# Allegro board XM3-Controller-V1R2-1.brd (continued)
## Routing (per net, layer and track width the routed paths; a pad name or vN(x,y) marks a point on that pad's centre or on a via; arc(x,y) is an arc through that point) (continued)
-15V: length 82
  TOP w0.178: CT81.1 242.56,22.11 ; CT81.1 240.3,23.56 ; CT81.1 242.56,22.84 ; CT81.1 241.43,23.64 ; CT81.1 242.56,23.56 ; CT81.1 240.3,22.84 ; CT81.1 240.3,22.11 ; CT81.1 241.43,22.03
  TOP w0.381: 255.78,5.18 J6.3 ; J6.3 254.66,6.3 ; J6.3 256.62,7.14 ; J6.3 256.9,6.3 ; J6.3 254.94,7.14 ; J6.3 255.78,7.42 ; J6.3 256.62,5.46 ; J6.3 254.94,5.46 ; 229.26,6.3 J4.3 ; J4.3 229.54,7.14 ; J4.3 229.54,5.46 ; J4.3 231.22,5.46 ; J4.3 231.22,7.14 ; J4.3 230.38,5.18 ; J4.3 230.38,7.42 ; J4.3 231.5,6.3 ; 242.24,5.46 J5.3 ; J5.3 241.96,6.3 ; J5.3 244.2,6.3 ; J5.3 243.92,5.46 ; J5.3 243.92,7.14 ; J5.3 243.08,5.18 ; J5.3 243.08,7.42 ; J5.3 242.24,7.14
  TOP w0.508: 238.38,13.03 238.21,13.2 DT11.2 ; RT121.2 v1(230.5,33.82)
  TOP w0.635: J10.7 4.39,31.19 3.55,30.36 3.55,27.76 5.33,25.99 12.85,25.99 CT76.1
  LAYER3 w0.508: v1(241.49,21.2) 241.49,25.92 236.73,30.69 233.63,30.69 v1(230.5,33.82)
  BOTTOM w0.178: J10.7 4.82,31.93 ; J10.7 5.4,31.77 ; J10.7 5.4,30.62 ; J10.7 4.09,31.19 ; J10.7 4.25,30.62 ; J10.7 5.56,31.19 ; J10.7 4.25,31.77 ; J10.7 4.82,30.46
  vias: v1(241.49,20.44) v1(241.49,19.68) v1(241.49,18.91) v1(241.49,18.15) v1(242.25,21.2) v1(242.25,20.44) v1(242.25,19.68) v1(242.25,18.91) v1(242.25,18.15) v1(243.01,21.2) v1(243.01,20.44) v1(243.01,19.68) v1(243.01,18.91) v1(243.01,18.15) v1(243.78,21.2) v1(243.78,20.44) v1(243.78,19.68) v1(243.78,18.91) v1(243.78,18.15) v1(244.54,21.2) v1(244.54,20.44) v1(244.54,19.68) v1(244.54,18.91) v1(244.54,18.15)
VIN: length 48.7
  TOP w0.178: QT2.5 25.3,6.34 ; QT2.5 24.22,6.89 ; QT2.5 24.22,6.34 ; QT2.5 25.3,7.45 ; QT2.5 25.3,6.89 ; QT2.5 24.76,7.45 ; QT2.5 24.76,6.34 ; QT2.5 24.22,7.45 ; 25.46,9.05 RT144.1 ; RT144.1 26.14,8.32 ; RT144.1 26.81,9.05 ; RT144.1 26.79,8.32 ; 24.22,5.07 QT2.6 ; QT2.6 24.22,5.62 ; QT2.6 24.22,6.18 ; QT2.6 25.3,5.07 ; QT2.6 24.76,6.18 ; QT2.6 25.3,5.62 ; QT2.6 25.3,6.18 ; QT2.6 24.76,5.07 ; QT2.8 25.3,3.08 ; QT2.8 24.22,3.08 ; QT2.8 24.22,3.64 ; QT2.8 25.3,2.53 ; QT2.8 24.76,2.53 ; QT2.8 24.76,3.64 ; QT2.8 24.22,2.53 ; QT2.8 25.3,3.64 ; QT2.7 25.3,3.8 ; QT2.7 25.3,4.91 ; QT2.7 24.76,4.91 ; QT2.7 24.22,3.8 ; QT2.7 24.22,4.91 ; QT2.7 24.76,3.8 ; QT2.7 24.22,4.35 ; QT2.7 25.3,4.35
  TOP w0.254: UT32.1 27.88,11.59 v1(27.37,12.1) ; RT136.1 v1(30.67,15.91)
  TOP w0.508: 12.69,6.93 J11.1 ; J11.1 13.71,6.58 ; J11.1 15.09,7.95 ; J11.1 13.71,9.33 ; J11.1 12.69,8.97 ; J11.1 12.34,7.95 ; J11.1 14.74,8.97 ; J11.1 14.74,6.93
  LAYER3 w0.254: v1(30.67,15.91) 30.67,15.4 v1(27.37,12.1) 28.38,11.09 v1(28.38,7.4)
0: length 1002.7
  TOP w0.178: 260.36,26.4 RT131.2 ; RT131.2 261.09,26.42 ; RT131.2 260.36,25.09 ; RT131.2 260.36,25.75 ; 237.83,28.99 CT74.1 ; CT74.1 239.22,29.72 ; CT74.1 239.21,28.99 ; CT74.1 238.52,30.45 ; CT74.1 237.81,29.72 ; CT74.1 237.83,30.45 ; CT74.1 239.21,30.45 ; 226.73,32.37 CT71.2 ; CT71.2 226.73,33.83 ; CT71.2 226.71,33.1 ; CT71.2 228.11,33.83 ; CT71.2 227.42,33.83 ; 247.55,27.55 CT79.1 ; CT79.1 247.55,28.24 ; CT79.1 247.55,26.86 ; CT79.1 248.28,26.85 ; CT75.2 248.94,29.64 ; CT75.2 247.55,29.64 ; CT75.2 247.54,28.91 ; CT75.2 247.55,28.18 ; CT75.2 248.25,29.64 ; CT75.2 248.95,28.91 ; 240.3,25.84 CT81.2 ; CT81.2 240.3,25.11 ; CT81.2 241.43,26.64 ; CT81.2 242.56,26.56 ; CT81.2 242.56,25.11 ; CT81.2 240.3,26.56 ; CT81.2 241.43,25.03 ; CT81.2 242.56,25.84 ; CT80.1 259.6,26.26 ; CT80.1 258.91,24.8 ; CT80.1 260.29,24.8 ; CT80.1 260.3,25.53 ; CT80.1 258.91,26.26 ; CT80.1 260.29,26.26 ; CT80.1 258.9,25.53 ; 237.84,28.45 RT126.1 ; RT126.1 239.17,29.18 ; RT126.1 239.2,28.45 ; RT126.1 237.86,29.18 ; 239.27,29.94 RT123.2 ; RT123.2 239.27,30.59 ; RT123.2 239.27,29.28 ; RT123.2 240,30.62 ; 226.73,32.43 CT73.1 ; CT73.1 226.73,31.05 ; CT73.1 226.73,31.74 ; CT73.1 227.46,31.04 ; RT134.1 260.28,24.26 ; RT134.1 258.92,24.26 ; RT134.1 260.26,24.99 ; RT134.1 258.94,24.99
  TOP w0.254: UT14.1 102.21,68 ; UT14.4 104.39,68.66 v1(104.65,68.91) ; UT15.1 108.81,68 ; v1(117.85,68.91) 117.6,68.66 UT16.4 ; v1(111.25,68.91) 111,68.66 UT15.4 ; CT86.2 33.77,15.77 v1(33.88,15.66) CT87.2 ; UT32.5 27.77,9.56 v1(27.56,9.35) ; CT88.2 v1(28.76,16.42) ; UT16.1 115.42,68
  TOP w0.381: UT23.8 108.23,45.02 108.2,45.04 ; 101.34,45.04 101.98,45.04 v1(102.61,44.4) ; 101.34,45.04 100.71,45.04 ; 101.34,45.04 101.35,45.04 UT22.1 ; v1(104.27,39.87) CT65.2 101.7,39.87 100.7,38.87 UT22.19 ; 100.71,45.04 100.32,45.04 100.05,44.77 UT22.3 ; 100.71,45.04 100.7,45.03 UT22.2 ; UT25.8 v1(185.6,37.62) ; UT24.8 130.75,38.23 131.19,37.8 v1(131.19,37.67) ; CT46.2 114.55,67.9 114.81,67.64 v1(115.06,67.64) 115.42,68 ; RT89.2 v1(130.3,65.77) 130.3,65.78 CT49.2 ; CT44.2 101.34,67.9 101.6,67.64 v1(101.85,67.64) 102.21,68 ; CT43.1 RT82.1 v1(125.18,73.07) ; UT22.10 v1(94.52,43.92) ; RT114.1 142.87,40.85 v1(143,40.97) ; v1(28.76,16.42) 28.68,16.33 27.94,16.33 26.14,14.53 RT140.2 ; 108.81,68 v1(108.46,67.64) 108.2,67.64 107.95,67.9 CT45.2 ; 109.47,45.04 109.53,44.99 UT23.6 ; 109.47,45.04 110.11,45.04 110.18,44.97 UT23.5 ; 109.47,45.04 108.84,45.04 ; CT60.2 v1(133.6,44.66) ; CT67.2 CT64.2 v1(174.5,39.58) ; 107.57,45.04 108.2,45.04 ; 107.57,45.04 106.55,45.04 106.14,44.63 v1(106.14,43.92) UT23.10 ; 107.57,45.04 107.58,45.03 UT23.9 ; 108.2,45.04 108.84,45.04 ; 181.32,45.47 181.32,48.94 UT13.20 ; 181.32,45.47 RT111.1 ; 181.32,45.47 180.99,45.8 v1(179.83,45.8) 179.54,45.8 CT61.2 ; 108.84,45.04 108.88,45 UT23.7 ; RT101.2 v1(122.33,59.82) ; UT19.8 v1(113.54,57.87) ; v1(115.66,39.87) CT66.2 114.39,39.83 112.77,39.83 112.13,39.18 UT23.19 ; CT50.2 v1(119,65.4) ; UT23.1 113.76,43.92 v1(114.17,43.51) ; UT20.8 v1(134.62,56.54)
  TOP w0.508: v1(121.65,83.32) CT18.1 122.07,81.93 UT6.2 ; RT37.1 94.21,82.56 CT14.2 v1(97.22,82.65) 97.22,81.88 97.24,81.86 97.24,81.39 CT19.2 97.26,81.03 96.71,80.49 UT10.2 ; UT9.2 166.74,81.05 166.19,81.59 CT22.2 165.84,81.58 165.37,81.58 165.34,81.55 v1(164.58,81.55) CT33.2 164.67,78.54 RT55.1 ; v1(101.9,83.32) CT15.1 102.32,81.93 UT3.2 ; UT11.4 v1(31.62,81.74) ; 189.19,61.75 189.48,62.04 UT18.2 ; 189.19,61.75 189.15,61.78 188.43,61.78 v1(188.34,61.87) ; 189.19,61.75 CT54.1 ; CT9.2 v1(116.21,84.47) ; v1(188.34,85.19) 188.43,85.1 189.15,85.1 189.19,85.07 ; UT5.2 115.49,81.93 CT17.1 v1(115.07,83.32) ; UT21.2 121.42,48.56 CT59.2 RT107.2 v1(121.42,52.42) ; 189.19,73.41 CT38.1 ; 189.19,73.41 189.48,73.7 UT12.2 ; 189.19,73.41 189.15,73.44 188.43,73.44 v1(188.34,73.53) ; UT8.2 158.14,81.05 157.59,81.59 CT21.2 157.24,81.58 156.77,81.58 156.74,81.55 v1(155.98,81.55) CT32.2 156.07,78.54 RT53.1 ; CT10.2 v1(122.79,84.47) ; CT7.2 v1(103.04,84.47) ; RT137.1 v1(230.29,13.2) ; UT7.2 149.54,81.05 149,81.59 CT20.2 148.64,81.58 148.17,81.58 148.14,81.55 v1(147.38,81.55) CT31.2 147.47,78.54 RT51.1 ; v1(188.34,96.85) 188.43,96.76 189.15,96.76 189.19,96.73 ; CT39.2 v1(30.14,70.82) UT17.1 ; UT2.2 189.48,85.36 189.19,85.07 ; DT3.2 DT2.2 ; DT2.2 v1(70.59,87.33) ; DT2.2 DT1.2 ; v1(108.48,83.32) CT16.1 108.9,81.93 UT4.2 ; RT4.1 v1(193.84,95.49) ; CT11.2 v1(150.36,83.53) ; CT48.2 v1(185.67,64.88) ; 189.19,96.73 CT3.1 ; 189.19,96.73 189.48,97.02 UT1.2 ; CT12.2 v1(158.95,83.53) ; CT8.2 v1(109.63,84.47) ; CT1.2 v1(185.67,99.86) ; DT12.2 v1(247.05,13.2) ; v1(227.16,35.88) RT117.2 CT69.2 231.02,35.88 UT28.2 ; 189.19,85.07 CT6.1 ; UT30.2 264.53,26.36 CT77.2 RT124.2 v1(263.4,29.03) ; CT4.2 v1(185.67,88.2) ; CT30.2 v1(99.2,79.67) ; CT35.2 v1(185.67,76.54) ; CT13.2 v1(167.55,83.53)
  TOP w0.635: CT72.2 CT76.2 18.14,27.53 v1(20.32,25.35) ; RT72.2 148.14,75.26 v1(146.56,75.26) ; v1(155.16,75.26) 156.74,75.26 RT73.2 ; v1(163.75,75.26) 165.34,75.26 RT74.2 ; v1(90.93,83.47) 90.93,81.89 RT36.2 ; UT27.2 74.76,38.81 75.38,39.44 CT62.2 CT68.2 ; UT26.2 57.92,38.81 CT63.2 CT70.2 ; 71.63,46.81 v1(69.98,46.81) ; DT4.2 v1(51.94,46.81)
  GND1 w0.178: J10.3 4.82,29.24 ; J10.3 5.41,28.65 ; J10.3 4.82,28.07 ; J10.3 4.24,28.65 ; J10.3 5.29,28.19 ; J10.3 5.29,29.12 ; J10.3 4.36,28.19 ; J10.3 4.36,29.12 ; 6.15,29.92 J10.5 ; J10.5 7.31,29.92 ; J10.5 6.73,30.51 ; J10.5 6.73,29.34 ; J10.5 7.19,29.46 ; J10.5 6.27,30.39 ; J10.5 7.19,30.39 ; J10.5 6.27,29.46 ; 6.73,39.5 J10.21 ; J10.21 7.31,40.08 ; J10.21 6.15,40.08 ; J10.21 7.19,40.55 ; J10.21 6.27,40.55 ; J10.21 6.73,40.67 ; J10.21 6.27,39.62 ; J10.21 7.19,39.62 ; UT13.84 152.6,95.71 ; UT13.84 153.44,95.43 ; UT13.84 153.44,93.75 ; UT13.84 153.72,94.59 ; UT13.84 151.76,95.43 ; UT13.84 151.76,93.75 ; UT13.84 151.48,94.59 ; UT13.84 152.6,93.47 ; J3.16 182.95,20.54 ; J3.16 182.95,22.22 ; J3.16 181.27,20.54 ; J3.16 182.11,20.26 ; J3.16 182.11,22.5 ; J3.16 183.23,21.38 ; J3.16 180.99,21.38 ; J3.16 181.27,22.22 ; 4.24,41.35 4.82,41.35 ; 4.82,41.35 5.41,41.35 ; 4.82,41.35 5.29,40.89 ; 4.82,41.35 5.29,41.82 ; 4.82,41.35 4.36,41.82 ; 4.82,41.35 4.82,40.77 ; 4.82,41.35 4.36,40.89 ; 4.82,41.35 4.82,41.94 ; 178.94,91.16 UT13.22 ; UT13.22 179.78,91.44 ; UT13.22 178.1,93.12 ; UT13.22 178.94,93.4 ; UT13.22 178.1,91.44 ; UT13.22 177.82,92.28 ; UT13.22 179.78,93.12 ; UT13.22 180.06,92.28 ; 183.81,22.22 J3.14 ; J3.14 185.49,22.22 ; J3.14 184.65,22.5 ; J3.14 184.65,20.26 ; J3.14 185.49,20.54 ; J3.14 183.53,21.38 ; J3.14 185.77,21.38 ; J3.14 183.81,20.54 ; 4.82,33.15 J10.11 ; J10.11 4.24,33.73 ; J10.11 5.41,33.73 ; J10.11 4.36,34.2 ; J10.11 5.29,34.2 ; J10.11 4.82,34.32 ; J10.11 4.36,33.27 ; J10.11 5.29,33.27 ; 74.35,22.22 J1.12 ; J1.12 76.31,21.38 ; J1.12 74.07,21.38 ; J1.12 74.35,20.54 ; J1.12 75.19,22.5 ; J1.12 75.19,20.26 ; J1.12 76.03,20.54 ; J1.12 76.03,22.22 ; 84.12,90.58 UT13.101 ; UT13.101 84.96,88.62 ; UT13.101 85.8,90.58 ; UT13.101 84.12,88.9 ; UT13.101 86.08,89.74 ; UT13.101 85.8,88.9 ; UT13.101 83.84,89.74 ; UT13.101 84.96,90.86 ; 117.14,48.26 UT13.60 ; UT13.60 117.14,49.94 ; UT13.60 117.98,47.98 ; UT13.60 118.82,49.94 ; UT13.60 116.86,49.1 ; UT13.60 117.98,50.22 ; UT13.60 119.1,49.1 ; UT13.60 118.82,48.26 ; 4.36,36.74 J10.15 ; J10.15 5.29,35.81 ; J10.15 4.36,35.81 ; J10.15 4.82,35.69 ; J10.15 5.41,36.27 ; J10.15 4.24,36.27 ; J10.15 5.29,36.74 ; J10.15 4.82,36.86 ; J1.2 87.89,22.5 ; J1.2 87.05,20.54 ; J1.2 89.01,21.38 ; J1.2 87.89,20.26 ; J1.2 88.73,22.22 ; J1.2 87.05,22.22 ; J1.2 86.77,21.38 ; J1.2 88.73,20.54 ; UT13.82 155.14,95.71 ; UT13.82 155.98,95.43 ; UT13.82 155.98,93.75 ; UT13.82 154.3,93.75 ; UT13.82 156.26,94.59 ; UT13.82 155.14,93.47 ; UT13.82 154.02,94.59 ; UT13.82 154.3,95.43 ; J1.16 70.11,22.5 ; J1.16 70.95,20.54 ; J1.16 70.11,20.26 ; J1.16 68.99,21.38 ; J1.16 70.95,22.22 ; J1.16 69.27,22.22 ; J1.16 69.27,20.54 ; J1.16 71.23,21.38 ; 130.07,21.38 J2.12 ; J2.12 132.31,21.38 ; J2.12 132.03,20.54 ; J2.12 130.35,20.54 ; J2.12 131.19,20.26 ; J2.12 132.03,22.22 ; J2.12 130.35,22.22 ; J2.12 131.19,22.5 ; 150.06,93.47 UT13.86 ; UT13.86 148.94,94.59 ; UT13.86 150.9,95.43 ; UT13.86 149.22,93.75 ; UT13.86 150.06,95.71 ; UT13.86 151.18,94.59 ; UT13.86 149.22,95.43 ; UT13.86 150.9,93.75 ; J2.16 127.23,21.38 ; J2.16 126.11,20.26 ; J2.16 125.27,20.54 ; J2.16 126.95,20.54 ; J2.16 124.99,21.38 ; J2.16 126.95,22.22 ; J2.16 125.27,22.22 ; J2.16 126.11,22.5 ; 89.2,48.26 UT13.104 ; UT13.104 90.04,50.22 ; UT13.104 91.16,49.1 ; UT13.104 90.88,49.94 ; UT13.104 89.2,49.94 ; UT13.104 90.04,47.98 ; UT13.104 88.92,49.1 ; UT13.104 90.88,48.26 ; 84.96,78.46 UT13.98 ; UT13.98 85.8,78.74 ; UT13.98 85.8,80.42 ; UT13.98 84.12,80.42 ; UT13.98 84.12,78.74 ; UT13.98 86.08,79.58 ; UT13.98 84.96,80.7 ; UT13.98 83.84,79.58 ; J10.17 6.73,38.13 ; J10.17 7.19,37.08 ; J10.17 6.73,36.96 ; J10.17 6.27,38.01 ; J10.17 6.15,37.54 ; J10.17 6.27,37.08 ; J10.17 7.31,37.54 ; J10.17 7.19,38.01 ; 72.65,20.26 J1.14 ; J1.14 72.65,22.5 ; J1.14 73.49,22.22 ; J1.14 73.49,20.54 ; J1.14 71.81,22.22 ; J1.14 71.81,20.54 ; J1.14 73.77,21.38 ; J1.14 71.53,21.38 ; 6.73,31.88 J10.9 ; J10.9 7.19,32.93 ; J10.9 7.31,32.46 ; J10.9 7.19,32 ; J10.9 6.15,32.46 ; J10.9 6.27,32.93 ; J10.9 6.27,32 ; J10.9 6.73,33.05 ; 127.81,22.22 J2.14 ; J2.14 127.81,20.54 ; J2.14 128.65,20.26 ; J2.14 128.65,22.5 ; J2.14 129.49,22.22 ; J2.14 129.77,21.38 ; J2.14 129.49,20.54 ; J2.14 127.53,21.38 ; 89.2,93.98 UT13.107 ; UT13.107 90.04,93.7 ; UT13.107 89.2,95.66 ; UT13.107 90.88,93.98 ; UT13.107 90.88,95.66 ; UT13.107 91.16,94.82 ; UT13.107 88.92,94.82 ; UT13.107 90.04,95.94 ; UT13.103 88.34,48.26 ; UT13.103 88.62,49.1 ; UT13.103 86.38,49.1 ; UT13.103 87.5,47.98 ; UT13.103 87.5,50.22 ; UT13.103 88.34,49.94 ; UT13.103 86.66,48.26 ; UT13.103 86.66,49.94 ; 146.68,95.43 UT13.88 ; UT13.88 148.64,94.59 ; UT13.88 148.36,93.75 ; UT13.88 147.52,93.47 ; UT13.88 147.52,95.71 ; UT13.88 146.68,93.75 ; UT13.88 148.36,95.43 ; UT13.88 146.4,94.59 ; UT13.20 181.48,50.22 ; UT13.20 180.64,49.94 ; UT13.20 181.48,47.98 ; UT13.20 182.32,48.26 ; UT13.20 182.32,49.94 ; UT13.20 180.36,49.1 ; UT13.20 180.64,48.26 ; UT13.20 182.6,49.1 ; J3.2 200.73,20.54 ; J3.2 199.05,22.22 ; J3.2 199.89,20.26 ; J3.2 198.77,21.38 ; J3.2 201.01,21.38 ; J3.2 199.05,20.54 ; J3.2 200.73,22.22 ; J3.2 199.89,22.5 ; 115.44,91.16 UT13.62 ; UT13.62 114.32,92.28 ; UT13.62 114.6,91.44 ; UT13.62 116.28,93.12 ; UT13.62 116.56,92.28 ; UT13.62 114.6,93.12 ; UT13.62 116.28,91.44 ; UT13.62 115.44,93.4 ; UT13.93 86.08,64.34 ; UT13.93 83.84,64.34 ; UT13.93 84.96,65.46 ; UT13.93 84.12,63.5 ; UT13.93 85.8,63.5 ; UT13.93 84.12,65.18 ; UT13.93 84.96,63.22 ; UT13.93 85.8,65.18 ; 142.77,21.38 J2.2 ; J2.2 144.73,22.22 ; J2.2 143.05,22.22 ; J2.2 145.01,21.38 ; J2.2 143.89,20.26 ; J2.2 143.05,20.54 ; J2.2 144.73,20.54 ; J2.2 143.89,22.5 ; 4.36,38.35 J10.19 ; J10.19 4.36,39.28 ; J10.19 5.29,38.35 ; J10.19 4.82,39.4 ; J10.19 5.29,39.28 ; J10.19 4.24,38.81 ; J10.19 5.41,38.81 ; J10.19 4.82,38.23 ; 186.07,21.38 J3.12 ; J3.12 187.19,20.26 ; J3.12 188.03,22.22 ; J3.12 186.35,20.54 ; J3.12 188.03,20.54 ; J3.12 186.35,22.22 ; J3.12 187.19,22.5 ; J3.12 188.31,21.38 ; UT13.106 88.34,93.98 ; UT13.106 87.5,95.94 ; UT13.106 88.34,95.66 ; UT13.106 86.38,94.82 ; UT13.106 86.66,93.98 ; UT13.106 86.66,95.66 ; UT13.106 88.62,94.82 ; UT13.106 87.5,93.7 ; 6.27,42.16 J10.25 ; J10.25 7.19,43.09 ; J10.25 7.31,42.62 ; J10.25 6.73,42.04 ; J10.25 6.27,43.09 ; J10.25 7.19,42.16 ; J10.25 6.15,42.62 ; J10.25 6.73,43.21 ; J10.13 6.73,35.59 ; J10.13 7.19,35.47 ; J10.13 7.19,34.54 ; J10.13 6.15,35 ; J10.13 7.31,35 ; J10.13 6.27,34.54 ; J10.13 6.73,34.42 ; J10.13 6.27,35.47 ; 8.63,28.65 9.1,28.19 ; 8.63,28.65 8.63,28.07 ; 8.63,28.65 8.63,29.24 ; 8.63,28.65 9.22,28.65 ; 8.63,28.65 8.17,28.19 ; 8.63,28.65 8.05,28.65 ; 8.63,28.65 9.1,29.12 ; 8.63,28.65 8.17,29.12
  GND1 w0.508: J11.2 8.74,6.93 ; J11.2 7.72,6.58 ; J11.2 8.74,8.97 ; J11.2 6.7,6.93 ; J11.2 6.35,7.95 ; J11.2 7.72,9.33 ; J11.2 6.7,8.97 ; J11.2 9.09,7.95 ; J11.3 10.72,4.63 ; J11.3 9.7,2.23 ; J11.3 12.09,3.25 ; J11.3 11.74,4.28 ; J11.3 11.74,2.23 ; J11.3 9.35,3.25 ; J11.3 10.72,1.88 ; J11.3 9.7,4.28
  GND1 w0.559: UT27.2 74.24,38.81 ; UT27.2 73.93,37.89 ; UT27.2 72.09,39.73 ; UT27.2 72.09,37.89 ; UT27.2 73.93,39.73 ; UT27.2 71.78,38.81 ; J12.2 44.66,7.24 ; J12.2 43.81,9.2 ; J12.2 42.97,7.24 ; J12.2 44.93,8.08 ; J12.2 42.7,8.08 ; J12.2 43.81,6.96 ; J12.2 44.66,8.92 ; J12.2 42.97,8.92 ; 42.97,17.3 J13.2 ; J13.2 44.93,16.46 ; J13.2 43.81,17.58 ; J13.2 42.97,15.62 ; J13.2 42.7,16.46 ; J13.2 44.66,17.3 ; J13.2 43.81,15.34 ; J13.2 44.66,15.62 ; UT26.2 56.15,37.89 ; UT26.2 54.31,39.73 ; UT26.2 56.15,39.73 ; UT26.2 54,38.81 ; UT26.2 56.46,38.81 ; UT26.2 54.31,37.89
  GND2 w0.178: 117.98,48.03 UT13.60 ; UT13.60 119.05,49.1 ; UT13.60 117.98,50.17 ; UT13.60 117.18,48.3 ; UT13.60 118.79,48.3 ; UT13.60 117.18,49.91 ; UT13.60 116.91,49.1 ; UT13.60 118.79,49.91 ; 84.96,63.27 UT13.93 ; UT13.93 84.16,63.54 ; UT13.93 85.77,65.15 ; UT13.93 84.96,65.41 ; UT13.93 83.89,64.34 ; UT13.93 85.77,63.54 ; UT13.93 86.03,64.34 ; UT13.93 84.16,65.15 ; 127.84,20.58 J2.14 ; J2.14 129.72,21.38 ; J2.14 127.58,21.38 ; J2.14 128.65,22.45 ; J2.14 128.65,20.31 ; J2.14 129.46,22.19 ; J2.14 127.84,22.19 ; J2.14 129.46,20.58 ; UT13.101 85.77,88.94 ; UT13.101 86.03,89.74 ; UT13.101 84.96,90.81 ; UT13.101 85.77,90.55 ; UT13.101 84.16,90.55 ; UT13.101 84.96,88.67 ; UT13.101 84.16,88.94 ; UT13.101 83.89,89.74 ; UT13.86 150.86,95.39 ; UT13.86 149.25,95.39 ; UT13.86 150.06,93.52 ; UT13.86 149.25,93.78 ; UT13.86 150.06,95.65 ; UT13.86 150.86,93.78 ; UT13.86 148.99,94.59 ; UT13.86 151.13,94.59 ; 126.11,20.31 J2.16 ; J2.16 125.04,21.38 ; J2.16 126.92,22.19 ; J2.16 125.3,20.58 ; J2.16 127.18,21.38 ; J2.16 125.3,22.19 ; J2.16 126.92,20.58 ; J2.16 126.11,22.45 ; 6.3,32.89 J10.9 ; J10.9 7.16,32.04 ; J10.9 7.16,32.89 ; J10.9 6.3,32.04 ; J1.12 76,20.58 ; J1.12 75.19,22.45 ; J1.12 76,22.19 ; J1.12 75.19,20.31 ; J1.12 76.26,21.38 ; J1.12 74.12,21.38 ; J1.12 74.38,22.19 ; J1.12 74.38,20.58 ; J10.5 7.16,30.35 ; J10.5 6.3,29.5 ; J10.5 7.16,29.5 ; J10.5 6.3,30.35 ; 6.3,42.2 J10.25 ; J10.25 7.16,42.2 ; J10.25 7.16,43.05 ; J10.25 6.3,43.05 ; UT13.22 179.75,93.09 ; UT13.22 178.14,91.48 ; UT13.22 179.75,91.48 ; UT13.22 177.87,92.28 ; UT13.22 178.94,91.21 ; UT13.22 180.01,92.28 ; UT13.22 178.94,93.35 ; UT13.22 178.14,93.09 ; 198.82,21.38 J3.2 ; J3.2 199.89,22.45 ; J3.2 200.7,20.58 ; J3.2 200.96,21.38 ; J3.2 199.89,20.31 ; J3.2 199.08,20.58 ; J3.2 199.08,22.19 ; J3.2 200.7,22.19 ; 143.08,20.58 J2.2 ; J2.2 143.89,20.31 ; J2.2 144.7,22.19 ; J2.2 144.7,20.58 ; J2.2 142.82,21.38 ; J2.2 143.08,22.19 ; J2.2 144.96,21.38 ; J2.2 143.89,22.45 ; J3.14 184.65,22.45 ; J3.14 183.84,22.19 ; J3.14 183.58,21.38 ; J3.14 185.46,22.19 ; J3.14 185.72,21.38 ; J3.14 185.46,20.58 ; J3.14 184.65,20.31 ; J3.14 183.84,20.58 ; 83.89,79.58 UT13.98 ; UT13.98 84.96,80.65 ; UT13.98 84.96,78.51 ; UT13.98 86.03,79.58 ; UT13.98 84.16,80.39 ; UT13.98 85.77,80.39 ; UT13.98 84.16,78.78 ; UT13.98 85.77,78.78 ; 152.6,93.52 UT13.84 ; UT13.84 153.67,94.59 ; UT13.84 152.6,95.65 ; UT13.84 153.4,95.39 ; UT13.84 153.4,93.78 ; UT13.84 151.53,94.59 ; UT13.84 151.79,93.78 ; UT13.84 151.79,95.39 ; UT13.20 182.29,48.3 ; UT13.20 181.48,50.17 ; UT13.20 180.41,49.1 ; UT13.20 180.68,49.91 ; UT13.20 182.29,49.91 ; UT13.20 180.68,48.3 ; UT13.20 182.55,49.1 ; UT13.20 181.48,48.03 ; 69.3,22.19 J1.16 ; J1.16 69.3,20.58 ; J1.16 70.11,20.31 ; J1.16 71.18,21.38 ; J1.16 70.11,22.45 ; J1.16 70.92,22.19 ; J1.16 70.92,20.58 ; J1.16 69.04,21.38 ; 4.4,33.31 J10.11 ; J10.11 5.25,34.16 ; J10.11 5.25,33.31 ; J10.11 4.4,34.16 ; 89.24,48.3 UT13.104 ; UT13.104 89.24,49.91 ; UT13.104 90.85,48.3 ; UT13.104 90.85,49.91 ; UT13.104 88.97,49.1 ; UT13.104 91.11,49.1 ; UT13.104 90.04,48.03 ; UT13.104 90.04,50.17 ; 6.3,39.66 J10.21 ; J10.21 7.16,39.66 ; J10.21 6.3,40.51 ; J10.21 7.16,40.51 ; 8.63,28.65 9.06,29.08 ; 8.63,28.65 8.21,29.08 ; 8.63,28.65 9.06,28.23 ; 8.63,28.65 8.21,28.23 ; UT13.62 116.25,91.48 ; UT13.62 116.51,92.28 ; UT13.62 114.64,91.48 ; UT13.62 114.64,93.09 ; UT13.62 115.44,91.21 ; UT13.62 115.44,93.35 ; UT13.62 116.25,93.09 ; UT13.62 114.37,92.28 ; J10.13 7.16,35.43 ; J10.13 6.3,34.58 ; J10.13 7.16,34.58 ; J10.13 6.3,35.43 ; 147.52,93.52 UT13.88 ; UT13.88 147.52,95.65 ; UT13.88 146.71,95.39 ; UT13.88 148.59,94.59 ; UT13.88 146.45,94.59 ; UT13.88 146.71,93.78 ; UT13.88 148.32,95.39 ; UT13.88 148.32,93.78 ; J10.15 5.25,35.85 ; J10.15 5.25,36.7 ; J10.15 4.4,35.85 ; J10.15 4.4,36.7 ; UT13.82 155.94,95.39 ; UT13.82 155.14,93.52 ; UT13.82 155.14,95.65 ; UT13.82 154.33,93.78 ; UT13.82 154.07,94.59 ; UT13.82 155.94,93.78 ; UT13.82 156.21,94.59 ; UT13.82 154.33,95.39 ; J1.14 72.65,22.45 ; J1.14 73.46,20.58 ; J1.14 71.84,22.19 ; J1.14 71.58,21.38 ; J1.14 73.46,22.19 ; J1.14 72.65,20.31 ; J1.14 71.84,20.58 ; J1.14 73.72,21.38 ; 89.24,94.02 UT13.107 ; UT13.107 90.85,95.63 ; UT13.107 89.24,95.63 ; UT13.107 91.11,94.82 ; UT13.107 90.85,94.02 ; UT13.107 88.97,94.82 ; UT13.107 90.04,95.89 ; UT13.107 90.04,93.75 ; 86.7,48.3 UT13.103 ; UT13.103 86.43,49.1 ; UT13.103 88.57,49.1 ; UT13.103 87.5,48.03 ; UT13.103 88.31,49.91 ; UT13.103 87.5,50.17 ; UT13.103 86.7,49.91 ; UT13.103 88.31,48.3 ; 4.4,29.08 J10.3 ; J10.3 4.4,28.23 ; J10.3 5.25,28.23 ; J10.3 5.25,29.08 ; 186.38,22.19 J3.12 ; J3.12 188,22.19 ; J3.12 187.19,22.45 ; J3.12 188,20.58 ; J3.12 186.38,20.58 ; J3.12 186.12,21.38 ; J3.12 188.26,21.38 ; J3.12 187.19,20.31 ; 181.3,22.19 J3.16 ; J3.16 181.3,20.58 ; J3.16 183.18,21.38 ; J3.16 182.92,22.19 ; J3.16 182.92,20.58 ; J3.16 181.04,21.38 ; J3.16 182.11,20.31 ; J3.16 182.11,22.45 ; J1.2 88.7,22.19 ; J1.2 88.96,21.38 ; J1.2 87.89,22.45 ; J1.2 87.08,22.19 ; J1.2 88.7,20.58 ; J1.2 86.82,21.38 ; J1.2 87.89,20.31 ; J1.2 87.08,20.58 ; J2.12 131.19,22.45 ; J2.12 132.26,21.38 ; J2.12 130.12,21.38 ; J2.12 131.19,20.31 ; J2.12 130.38,20.58 ; J2.12 132,20.58 ; J2.12 130.38,22.19 ; J2.12 132,22.19 ; 4.4,38.39 J10.19 ; J10.19 5.25,39.24 ; J10.19 5.25,38.39 ; J10.19 4.4,39.24 ; 4.82,41.35 5.25,41.78 ; 4.82,41.35 5.25,40.93 ; 4.82,41.35 4.4,40.93 ; 4.82,41.35 4.4,41.78 ; 87.5,93.75 UT13.106 ; UT13.106 86.43,94.82 ; UT13.106 87.5,95.89 ; UT13.106 88.31,95.63 ; UT13.106 86.7,95.63 ; UT13.106 88.31,94.02 ; UT13.106 88.57,94.82 ; UT13.106 86.7,94.02 ; J10.17 7.16,37.97 ; J10.17 7.16,37.12 ; J10.17 6.3,37.97 ; J10.17 6.3,37.12
  GND2 w0.508: J11.2 8.71,8.94 ; J11.2 6.4,7.95 ; J11.2 7.72,9.27 ; J11.2 6.74,8.94 ; J11.2 7.72,6.63 ; J11.2 8.71,6.97 ; J11.2 9.04,7.95 ; J11.2 6.74,6.97 ; J11.3 11.7,4.24 ; J11.3 11.7,2.27 ; J11.3 10.72,1.93 ; J11.3 9.73,2.27 ; J11.3 9.4,3.25 ; J11.3 9.73,4.24 ; J11.3 12.04,3.25 ; J11.3 10.72,4.58
  GND2 w0.559: UT26.2 56.12,37.93 ; UT26.2 54.35,39.7 ; UT26.2 56.41,38.81 ; UT26.2 56.12,39.7 ; UT26.2 54.35,37.93 ; UT26.2 54.05,38.81 ; J13.2 43.81,17.53 ; J13.2 44.62,17.27 ; J13.2 44.88,16.46 ; J13.2 44.62,15.66 ; J13.2 43.81,15.39 ; J13.2 42.75,16.46 ; J13.2 43.01,15.66 ; J13.2 43.01,17.27 ; UT27.2 74.19,38.81 ; UT27.2 73.9,37.93 ; UT27.2 71.83,38.81 ; UT27.2 72.13,37.93 ; UT27.2 72.13,39.7 ; UT27.2 73.9,39.7 ; J12.2 43.81,9.15 ; J12.2 43.01,8.89 ; J12.2 44.62,8.89 ; J12.2 44.88,8.08 ; J12.2 43.81,7.01 ; J12.2 44.62,7.27 ; J12.2 43.01,7.27 ; J12.2 42.75,8.08
  BOTTOM w0.381: CB20.2 143.55,44.53 v1(144.27,44.53) ; v1(143,40.97) 143.55,40.43 CB22.2 ; CB23.2 134.78,38.22 134.11,37.54 131.32,37.54 v1(131.19,37.67) ; CB21.2 134.78,43.47 v1(133.6,44.66)
  BOTTOM w0.508: CB12.2 CB11.2 v1(100.32,87.97) CB10.2 CB9.2 ; UB3.2 v1(104.08,57.74) ; UT13.62 115.7,92.03 115.7,89.61 114.05,87.97 CB8.2 ; CB5.2 CB6.2 CB7.2 157.64,88.43 v1(156.59,89.49) ; CB19.2 v1(96.86,59.3)
  BOTTOM w0.635: v1(175.89,89.36) 175.06,88.52 CB1.2 CB2.2 CB3.2 CB4.2 ; UB2.3 140.47,75.37 141.33,75.37 141.8,75.84 CB15.2 143.36,74.39 CB18.2 ; UB2.3 v1(140.44,73.97) ; UB2.3 138.02,75.34 CB16.2 ; CB17.2 192.89,74.9 CB13.2 191.33,76.35 190.86,75.88 190,75.88 UB1.3 187.55,75.85 CB14.2 185.87,76.35 v1(185.67,76.54)
  vias: v1(223.96,27.41) v1(223.96,26.65) v1(224.72,27.41) v1(224.72,26.65) v1(226.82,22.57) v1(227.58,22.57) v1(228.34,22.57) v1(228.34,21.8) v1(228.34,21.04) v1(228.34,20.28) v1(231.65,29.68) v1(231.65,28.92) v1(231.65,28.16) v1(231.65,27.39) v1(231.65,26.63) v1(232.41,29.68) v1(232.41,28.92) v1(232.41,28.16) v1(232.41,27.39) v1(232.41,26.63) v1(233.18,29.68) v1(233.18,28.92) v1(233.18,28.16) v1(233.18,27.39) v1(233.18,26.63) v1(233.94,29.68) v1(233.94,28.92) v1(233.94,28.16) v1(233.94,27.39) v1(233.94,26.63) v1(236.51,26.83) v1(236.51,26.07) v1(236.51,25.31) v1(237.27,26.83) v1(237.27,26.07) v1(237.27,25.31) v1(238.03,26.83) v1(238.03,26.07) v1(238.03,25.31) v1(238.79,26.83) v1(238.79,26.07) v1(238.79,25.31) v1(245.04,23.22) v1(245.04,22.46) v1(245.81,23.22) v1(245.81,22.46) v1(252.73,25.49) v1(252.73,24.73) v1(252.73,23.96) v1(252.73,23.2) v1(252.73,22.44) v1(253.5,25.49) v1(253.5,24.73) v1(253.5,23.96) v1(253.5,23.2) v1(253.5,22.44) v1(254.26,25.49) v1(254.26,24.73) v1(254.26,23.96) v1(254.26,23.2) v1(254.26,22.44) v1(255.02,25.49) v1(255.02,24.73) v1(255.02,23.96) v1(255.02,23.2) v1(255.02,22.44) v1(259.19,22.61) v1(259.19,21.85) v1(259.95,22.61) v1(259.95,21.85)
1: length 91.4
  TOP w0.508: CT47.2 18.68,66.89 20.45,68.66 UT17.4 19.68,70.82 v1(18.71,71.8) 17.27,71.8 CT37.2 ; UT11.5 v1(16.25,81.74)
  GND1 w0.178: J9.5 11.85,68.74 ; J9.5 10.92,67.81 ; J9.5 10.21,68.03 ; J9.5 10.21,69.44 ; J9.5 11.63,69.44 ; J9.5 10.92,69.66 ; J9.5 9.99,68.74 ; J9.5 11.63,68.03 ; 9.99,74.22 J9.3 ; J9.3 11.63,74.93 ; J9.3 10.92,73.29 ; J9.3 11.85,74.22 ; J9.3 10.21,74.93 ; J9.3 11.63,73.51 ; J9.3 10.92,75.15 ; J9.3 10.21,73.51
  GND1 w0.508: J9.11 9.55,63.76 ; J9.11 8.17,63.26 ; J9.11 10.93,63.26 ; J9.11 10.93,60.5 ; J9.11 7.67,61.88 ; J9.11 11.43,61.88 ; J9.11 9.55,60 ; J9.11 8.17,60.5 ; J9.10 10.93,87.95 ; J9.10 9.55,84.69 ; J9.10 11.43,86.57 ; J9.10 8.17,85.19 ; J9.10 8.17,87.95 ; J9.10 10.93,85.19 ; J9.10 9.55,88.45 ; J9.10 7.67,86.57
  GND2 w0.178: J9.5 11.59,68.06 ; J9.5 11.8,68.74 ; J9.5 10.92,67.86 ; J9.5 10.04,68.74 ; J9.5 10.25,68.06 ; J9.5 11.59,69.41 ; J9.5 10.25,69.41 ; J9.5 10.92,69.61 ; J9.3 11.8,74.22 ; J9.3 11.59,74.89 ; J9.3 10.92,75.1 ; J9.3 11.59,73.55 ; J9.3 10.92,73.34 ; J9.3 10.04,74.22 ; J9.3 10.25,74.89 ; J9.3 10.25,73.55
  GND2 w0.508: 8.2,60.53 J9.11 ; J9.11 8.2,63.22 ; J9.11 10.89,63.22 ; J9.11 10.89,60.53 ; 8.2,87.91 J9.10 ; J9.10 8.2,85.22 ; J9.10 10.89,85.22 ; J9.10 10.89,87.91
A-CURRENT: length 4.2
  TOP w0.508: RT15.2 UT13.30
  BOTTOM w0.508: CB7.1 UT13.30
A-FAULT: length 28.3
  TOP w0.381: UT19.3 112.1,61.11 v1(113.54,61.11)
  BOTTOM w0.508: UT13.80 117.98,58.33 115.2,61.11 v1(113.54,61.11) 113.51,61.14 106.02,61.14 104.65,59.77 100.88,59.77 100.37,59.26 UB3.6
A-FAULT-N: length 56.6
  TOP w0.254: LT1.1 104.79,63.08 104.43,63.08 v1(104.19,63.33)
  LAYER3 w0.254: v1(104.19,63.33) 103.99,63.12 103.99,62.26 103.81,62.08 103.81,61.24 99.8,57.23 94.32,57.23 93.01,55.92 93.01,37.11 83.23,27.33 83.23,26.9 82.35,26.05 81.47,25.18 81.47,24.91 81.46,24.9 81.46,22.57 J1.8
A-FAULT-N-FILTER: length 5.4
  TOP w0.381: UT19.1 110.91,63.6 RT91.2
  TOP w0.508: LT1.2 108.48,63.68 CT52.2 RT91.2
A-FAULT-P: length 53.8
  TOP w0.254: v1(103.38,62.51) 105.11,62.51 105.4,62.22 LT3.1
  LAYER3 w0.254: J1.7 80.27,24.6 82.03,26.35 82.8,27.09 82.8,27.51 92.58,37.29 92.58,56.1 94.14,57.66 99.62,57.66 103.38,61.42 v1(103.38,62.51)
A-FAULT-P-FILTER: length 5
  TOP w0.381: RT91.1 110.19,61.78 UT19.2
  TOP w0.508: RT91.1 CT52.1 108.48,61.91 LT3.2
A-LEN: length 32.3
  TOP w0.381: J1.13 72.65,27.74 74.44,29.53 88.91,29.53 96.15,36.76 UT22.12
A-LEN-OUT: length 5.5
  TOP w0.381: UT22.8 96.8,48.24 UT13.52
A-OCEN: length 33.1
  TOP w0.381: UT22.11 95.5,37.03 88.64,30.18 74.17,30.18 70.11,26.12 J1.15
A-OCEN-OUT: length 5.6
  TOP w0.381: UT22.9 96.15,48.07 UT13.51
A-PSDIS: length 43.1
  TOP w0.381: UT23.16 110.18,37.11 109.73,36.65 v1(103.38,36.65) ; J1.11 75.19,26.88 77.09,28.78 89.41,28.78 v1(95.76,35.13)
  BOTTOM w0.381: v1(95.76,35.13) 100.71,35.13 102.23,36.65 v1(103.38,36.65)
A-PSDIS-OUT: length 6
  TOP w0.381: UT23.4 110.83,47.03 UT13.58
A-RTD: length 49.2
  TOP w0.254: 103.38,67.48 UT14.2
  TOP w0.381: 105.92,68.36 106.03,68.48 106.55,68.48 106.93,68.1 v1(106.93,67.62) 106.93,66.12 107.82,65.23 111.08,65.23 114.55,61.76 114.55,60.21 114.17,59.82 UT19.5 ; 105.92,68.36 105.92,67.63 105.54,67.25 103.61,67.25 103.38,67.48 ; 105.92,68.36 RT84.1
  LAYER3 w0.381: UT13.46 106.56,93.54 106.56,91.76 107.2,91.12 107.2,83.15 106.93,82.88 v1(106.93,67.62)
A-RTD-N: length 59.1
  TOP w0.254: v1(101.73,60.68) 102.11,60.68 104.64,58.15 104.69,58.15 104.7,58.15 104.7,57.97 104.88,57.79 105.05,57.79 105.45,57.4 LT7.1
  LAYER3 w0.254: J1.10 77.73,22.23 78.92,23.43 78.92,24.69 91.74,37.51 91.74,57.56 95.22,61.04 101.09,61.04 101.45,60.68 v1(101.73,60.68)
A-RTD-N-FILTER: length 5.5
  TOP w0.381: UT19.7 111.24,58.52 110.02,57.3 RT102.2
  TOP w0.508: LT7.2 108.53,57.08 CT55.2 RT102.2
A-RTD-P: length 57
  TOP w0.254: LT5.1 105.17,58.59 104.81,58.59 101.73,61.67 v1(101.73,61.83)
  LAYER3 w0.254: v1(101.73,61.83) 101.37,61.47 95.05,61.47 91.31,57.74 91.31,37.69 78.84,25.22 78.61,25.22 77.73,24.34 J1.9
A-RTD-P-FILTER: length 5.1
  TOP w0.381: RT102.1 110.42,59.17 UT19.6
  TOP w0.508: RT102.1 CT55.1 108.53,58.86 LT5.2
A-TEMP: length 5.2
  TOP w0.508: RT24.2 UT13.69
  BOTTOM w0.508: CB11.1 UT13.69
AHS-PWM: length 57
  BOTTOM w0.381: RB28.1 135.51,41.86 136.14,42.5 136.14,44.66 137.29,45.8 137.29,46.69 146.43,55.83 179.07,55.83 181.48,53.42 UT13.40
AHS-PWM-N: length 59.4
  TOP w0.254: UT24.3 129.5,41.95 129.08,42.37 v1(125.98,42.37)
  LAYER3 w0.254: v1(125.98,42.37) 125.7,42.37 125.4,42.06 125.4,35.97 119.18,29.75 90.98,29.75 86.54,25.31 86.54,23.43 85.35,22.23 J1.4
AHS-PWM-P: length 58.1
  TOP w0.254: v1(125.98,43.52) 126.7,42.8 129.26,42.8 129.48,42.58 129.5,42.6 UT24.2
  LAYER3 w0.254: J1.3 85.35,24.72 90.8,30.18 119,30.18 124.97,36.15 124.97,42.24 125.98,43.26 v1(125.98,43.52)
ALS-PWM: length 54.3
  BOTTOM w0.381: RB29.1 136.27,40.08 137.16,40.97 137.16,42.88 138.56,44.27 138.56,45.42 148.41,55.27 176.33,55.27 178.94,52.66 UT13.39
ALS-PWM-N: length 61.3
  TOP w0.254: v1(124.2,40.9) 124.59,40.52 125.02,40.52 125.78,39.75 128.83,39.75 129.72,40.65 UT24.5
  LAYER3 w0.254: J1.6 84,22.57 84,24.8 84.82,25.62 84.82,26.76 89.2,31.14 118.67,31.14 123.82,36.3 123.82,39.65 124,39.83 124,40.69 v1(124.2,40.9)
ALS-PWM-P: length 58.2
  TOP w0.254: UT24.6 129.68,40 129.01,39.32 125.6,39.32 124.84,40.08 v1(123.39,40.08)
  LAYER3 w0.254: v1(123.39,40.08) 123.39,36.48 118.49,31.57 89.02,31.57 84.39,26.94 84.39,25.79 82.81,24.22 J1.5
B-CURRENT: length 4.2
  TOP w0.508: RT16.2 UT13.29
  BOTTOM w0.508: CB6.1 UT13.29
B-FAULT: length 21.3
  TOP w0.381: v1(114.81,56.72) 114.81,57.1 116.88,59.17 UT19.11
  BOTTOM w0.508: UB3.3 114.74,56.78 v1(114.81,56.72) 115.44,56.09 UT13.79
B-FAULT-N: length 43.9
  TOP w0.254: LT8.1 124.6,56.63 125.59,57.62 v1(126.48,57.62)
  LAYER3 w0.254: J2.8 136.27,22.23 137.46,23.43 137.46,28.58 135.79,30.26 135.79,31.48 129.61,37.65 129.61,47.94 126.24,51.32 126.24,57.38 v1(126.48,57.62)
B-FAULT-N-FILTER: length 5.9
  TOP w0.381: UT19.9 118.36,57.87 118.78,57.46 118.78,56.88 119.08,56.58 RT103.2
  TOP w0.508: RT103.2 CT56.2 122.73,56.58 LT8.2
B-FAULT-P: length 42.3
  TOP w0.254: LT6.1 126.13,58.27 126.48,58.61 v1(126.48,58.77)
  LAYER3 w0.254: v1(126.48,58.77) 125.81,58.1 125.81,51.14 129.18,47.76 129.18,37.47 135.36,31.3 135.36,30.08 137.03,28.4 137.03,24.84 136.27,24.08 J2.7
B-FAULT-P-FILTER: length 5.2
  TOP w0.381: RT103.1 119.68,58.52 UT19.10
  TOP w0.508: RT103.1 CT56.1 121.51,58.27 LT6.2
B-LEN: length 40.5
  TOP w0.381: UT22.14 97.45,35.6 100.15,32.9 123.11,32.9 128.65,27.36 J2.13
B-LEN-OUT: length 8
  TOP w0.381: UT13.54 100.96,47.32 99.44,47.32 98.1,45.98 UT22.6
B-OCEN: length 39.7
  TOP w0.381: J2.15 126.11,29.11 122.88,32.34 99.92,32.34 96.8,35.46 UT22.13
B-OCEN-OUT: length 6.3
  TOP w0.381: UT22.7 97.45,46.35 UT13.53
B-PSDIS: length 29.4
  TOP w0.381: UT23.17 v1(110.83,36.53) ; J2.11 131.19,25.61 123.34,33.45 111.66,33.45 110.83,34.28 v1(110.83,34.37)
  BOTTOM w0.381: v1(110.83,36.53) v1(110.83,34.37)
B-PSDIS-OUT: length 7.5
  TOP w0.381: UT23.3 111.48,46.28 112.14,46.94 113.28,46.94 UT13.59
B-RTD: length 45.3
  TOP w0.254: UT15.2 109.98,67.48
  TOP w0.381: UT19.13 117.21,60.48 117.15,60.53 116.96,60.53 116.62,60.88 116.62,61.07 115.95,61.73 115.95,62.69 113.66,64.98 v1(113.66,67.44) 113.66,67.96 113.03,68.6 RT85.1 112.52,68.36 ; 112.52,68.36 112.52,67.63 112.14,67.25 110.21,67.25 109.98,67.48 ; 112.52,68.36 112.64,68.48
  LAYER3 w0.381: v1(113.66,67.44) 113.66,69.93 111.38,72.21 111.38,87.07 109.1,89.35 109.1,93.54 UT13.45
B-RTD-N: length 47.5
  TOP w0.254: LT2.1 125.33,63.09 v1(125.6,62.82)
  LAYER3 w0.254: J2.10 134.92,22.57 134.92,31.12 128.75,37.29 128.75,47.58 125.37,50.96 125.37,60.58 126.21,61.42 126.21,61.93 125.6,62.54 v1(125.6,62.82)
B-RTD-N-FILTER: length 5.7
  TOP w0.381: RT92.2 119.82,63 118.59,61.78 UT19.15
  TOP w0.508: LT2.2 122.79,63.2 121.69,63.2 CT53.2 RT92.2
B-RTD-P: length 43.4
  TOP w0.254: LT4.1 125.24,61.31 v1(125.6,61.67)
  LAYER3 w0.254: v1(125.6,61.67) 125.6,61.42 124.94,60.76 124.94,50.78 128.32,47.4 128.32,37.11 134.49,30.94 134.49,25.22 133.73,24.46 J2.9
B-RTD-P-FILTER: length 5.3
  TOP w0.381: RT92.1 119.23,61.4 118.95,61.13 UT19.14
  TOP w0.508: LT4.2 121.59,61.31 CT53.1 RT92.1
B-TEMP: length 5.2
  TOP w0.508: RT25.2 UT13.67
  BOTTOM w0.508: CB10.1 UT13.67
BHS-PWM: length 55.4
  BOTTOM w0.381: UT13.38 176.4,52.02 173.71,54.71 149.36,54.71 139.55,44.91 139.55,43.03 140.46,42.12 144.4,42.12 144.78,41.73 144.78,37.92 144.14,37.29 RB30.1
BHS-PWM-N: length 23.9
  TOP w0.254: UT24.11 137.7,40 137.81,39.89 139.51,39.89 139.77,39.63 v1(140.64,39.63)
  LAYER3 w0.254: v1(140.64,39.63) 140.64,39.12 142.54,37.22 142.54,23.43 141.35,22.23 J2.4
BHS-PWM-P: length 20.2
  TOP w0.254: v1(139.83,38.81) 139.83,38.96 139.33,39.46 137.81,39.46 137.7,39.35 UT24.10
  LAYER3 w0.254: v1(139.83,38.81) 140.33,38.81 142.11,37.04 142.11,25.1 141.35,24.34 J2.3
BLS-PWM: length 39.1
  BOTTOM w0.381: RB27.1 145.16,43.51 146.81,45.16 146.81,50.21 150.76,54.16 171.35,54.16 UT13.37
BLS-PWM-N: length 23.5
  TOP w0.254: UT24.13 136.57,41.42 137.25,41.42 137.31,41.48 138.81,41.48 v1(138.94,41.35)
  LAYER3 w0.254: v1(138.94,41.35) 138.94,37.77 140,36.71 140,22.57 J2.6
BLS-PWM-P: length 21.1
  TOP w0.254: v1(138.12,42.17) 138.12,41.91 137.36,41.91 137.33,41.95 UT24.14
  LAYER3 w0.254: J2.5 138.81,24.21 139.57,24.97 139.57,36.53 138.51,37.59 138.51,40.92 138.33,41.1 138.33,41.33 138.12,41.53 v1(138.12,42.17)
C-CURRENT: length 4.2
  TOP w0.508: RT17.2 UT13.28
  BOTTOM w0.508: CB5.1 UT13.28
C-FAULT: length 39.1
  TOP w0.381: 130.17,57.81 130.34,57.65 UT20.3
  TOP w0.508: 130.17,57.81 130.03,57.96 128.49,57.96 125.73,55.2 v1(112.01,55.2)
  BOTTOM w0.508: UT13.78 112.9,54.31 v1(112.01,55.2) 102.49,55.2 101.68,56 101.68,58.33 102.04,58.69 UB3.1
C-FAULT-N: length 81.7
  TOP w0.254: LT9.1 127.76,48.99 128.43,48.31 128.43,47.83 128.94,47.32 135.01,47.32 v1(136.28,48.59)
  LAYER3 w0.254: J3.8 193.46,22.57 193.46,24.42 189.1,28.78 167.06,28.78 148.11,47.73 136.71,47.73 136.28,48.16 v1(136.28,48.59)
C-FAULT-N-FILTER: length 5.6
  TOP w0.381: UT20.1 129.04,55.59 127.85,54.4 RT104.2
  TOP w0.508: LT9.2 127.85,51.6 CT57.2 RT104.2
C-FAULT-P: length 77.4
  TOP w0.254: LT10.1 129.54,48.99 128.87,48.31 128.87,48.01 129.12,47.75 134.83,47.75 135.13,48.05 v1(135.13,48.59)
  LAYER3 w0.254: v1(135.13,48.59) 136.42,47.3 147.93,47.3 166.88,28.35 188.92,28.35 192.67,24.6 192.67,24.35 192.27,23.95 J3.7
C-FAULT-P-FILTER: length 5.2
  TOP w0.381: 129.45,54.31 129.45,54.73 129.69,54.97 UT20.2
  TOP w0.508: 129.45,54.31 CT57.1 129.54,52.82 LT10.2
C-LEN: length 93.6
  TOP w0.381: J3.13 184.65,25.67 179.68,30.63 129.82,30.63 125.28,35.18 112.68,35.18 112.1,35.77 99.6,35.77 98.75,36.61 UT22.16
C-LEN-OUT: length 13.9
  TOP w0.381: UT22.4 99.4,45.25 99.95,45.8 107.06,45.8 UT13.57
C-OCEN: length 93
  TOP w0.381: UT22.15 98.1,36.35 99.31,35.13 111.89,35.13 112.39,34.62 125.04,34.62 129.59,30.08 179.45,30.08 182.24,27.29 182.24,24.05 J3.15
C-OCEN-OUT: length 9.7
  TOP w0.381: UT13.55 102.74,46.56 99.69,46.56 98.75,45.62 UT22.5
C-PSDIS: length 82
  TOP w0.381: UT23.18 111.48,37.18 112.92,35.74 125.51,35.74 130.05,31.19 179.92,31.19 J3.11
C-PSDIS-OUT: length 16.8
  TOP w0.254: UT13.74 104,50.38 106.03,50.38 106.54,49.88 v1(106.54,47.07)
  TOP w0.381: UT23.2 112.13,44.77 v1(113.16,45.8)
  BOTTOM w0.381: v1(113.16,45.8) 107.7,45.8 106.54,46.95 v1(106.54,47.07)
C-RTD: length 52.7
  TOP w0.254: UT16.2 116.58,67.48
  TOP w0.381: 119.12,68.36 119.12,67.63 118.74,67.25 116.81,67.25 116.58,67.48 ; 119.12,68.36 119.24,68.48 ; 119.12,68.36 RT86.1 119.24,68.48 ; 119.24,68.48 119.45,68.28 v1(121.54,68.28) 126.74,63.07 126.74,61.93 128.27,60.4 129.43,60.4 131.64,58.19 UT20.5
  LAYER3 w0.381: UT13.42 116.72,93.54 116.72,91.76 117.6,90.88 117.6,82.5 121.54,78.56 v1(121.54,68.28)
C-RTD-N: length 72.6
  TOP w0.254: v1(133.86,48.59) 133.86,49.46 LT12.1
  LAYER3 w0.254: J3.10 190.92,22.57 190.92,24.55 190.68,24.79 190.68,25.73 188.49,27.92 166.7,27.92 147.75,46.87 135.33,46.87 134.03,48.16 134.03,48.42 v1(133.86,48.59)
C-RTD-N-FILTER: length 5.5
  TOP w0.381: UT20.7 132.94,55.77 134.04,54.67 RT105.2
  TOP w0.508: LT12.2 134.13,52.82 CT58.2 RT105.2
C-RTD-P: length 70.3
  TOP w0.254: v1(132.71,48.59) 132.86,48.75 132.86,49.23 LT11.1
  LAYER3 w0.254: v1(132.71,48.59) 132.99,48.59 135.15,46.43 147.57,46.43 166.52,27.49 188.31,27.49 190.24,25.55 190.24,24.97 189.73,24.46 J3.9
C-RTD-P-FILTER: length 5.1
  TOP w0.381: RT105.1 132.44,55.09 132.29,55.24 UT20.6
  TOP w0.508: LT11.2 132.35,52.82 CT58.1 RT105.1
C-TEMP: length 5.2
  TOP w0.508: RT26.2 UT13.66
  BOTTOM w0.508: CB9.1 UT13.66
CANA-H: length 12.8
  TOP w0.508: 19.37,76.66 18.35,77.68 16.8,77.68 RT50.1 15.84,77.55 13.59,77.55 11.63,75.59 J9.7
CANA-L: length 9.7
  TOP w0.508: J9.2 12.03,76.96 13.3,78.23 15.71,78.23 16.2,78.73 RT50.2 16.31,78.73 16.45,78.59 16.48,78.59 16.71,78.36 18.53,78.36 UT11.6
CANA-RX: length 164.5
  TOP w0.508: 28.89,76.66 31.24,76.66 32.26,77.68 43.17,77.68 67.61,102.12 119.21,102.12 128.15,93.17 138.92,93.17 143.65,97.9 173.72,97.9 174.25,97.37 174.25,95.21 UT13.4
CANA-TX: length 166.2
  TOP w0.508: UT13.3 176.4,96.47 174.09,98.79 143.28,98.79 138.56,94.06 128.52,94.06 119.57,103.01 67.24,103.01 42.8,78.56 32.26,78.56 31.62,79.2 UT11.3
CANBH: length 100.3
  LAYER3 w0.254: 83.91,85.59 84.03,85.59 UT13.99
  LAYER3 w0.381: 83.91,85.59 67.3,85.59 16.81,35.09 16.81,32.81 12.07,28.07 11.23,28.07 J10.2
CANBL: length 104.3
  LAYER3 w0.254: UT13.100 83.91,86.15
  LAYER3 w0.381: J10.1 9.02,27.38 10.26,28.63 11.84,28.63 16.25,33.05 16.25,35.33 67.07,86.15 83.91,86.15
CASE-LED1: length 20.4
  TOP w0.508: UT13.76 107.82,52.91 108.58,53.67 122.3,53.67 123.19,52.78 123.19,51.41 RT107.1 124.21,51.24 RT108.1
CASE-TEMP: length 5.2
  TOP w0.508: RT27.2 UT13.63
  BOTTOM w0.508: CB8.1 UT13.63
CHS-PWM: length 18.9
  TOP w0.381: RT118.1 175.13,36.27 172.34,39.07 172.34,42.5 170.05,44.78 170.05,50.75 170.94,51.64 UT13.36
CHS-PWM-N: length 28.1
  TOP w0.254: UT25.3 181.52,36.06 v1(181.48,36.02)
  LAYER3 w0.254: J3.4 198.54,22.57 198.54,24.78 192.96,30.36 186.07,30.36 181.12,35.3 181.12,35.66 v1(181.48,36.02)
CHS-PWM-P: length 25
  TOP w0.254: UT25.2 180.87,36.56 v1(180.33,36.02)
  LAYER3 w0.254: v1(180.33,36.02) 180.69,35.66 180.69,35.12 185.89,29.92 192.78,29.92 197.35,25.36 J3.3
CLS-PWM: length 17.4
  TOP w0.381: RT113.1 175.86,44.57 172.58,47.84 172.58,52.42 171.96,53.04 170.18,53.04 UT13.35
CLS-PWM-N: length 21.2
  TOP w0.254: J3.6 194.81,21.8 193.55,23.07 193.55,25.43 182.94,36.03 182.94,37.49 UT25.5
CLS-PWM-P: length 18.5
  TOP w0.254: UT25.6 183.38,37.52 183.38,36.21 194.81,24.77 J3.5
EXT-CURRENT: length 5.2
  TOP w0.508: RT23.2 UT13.70
  BOTTOM w0.508: CB12.1 UT13.70
GLOBAL-FAULT: length 5.2
  BOTTOM w0.508: UT13.73 100.37,51.81 UB3.4
IA-M: length 113.7
  TOP w0.508: RT62.1 150.18,72.92 149.57,72.31 148.14,72.31
  TOP w0.635: v1(148.08,70.06) 148.08,72.24 148.14,72.31 RT72.1
  LAYER3 w0.635: J4.2 227.84,9.36 174.26,62.94 155.19,62.94 v1(148.08,70.06)
IB-M: length 117.5
  TOP w0.508: 156.74,72.31 158.16,72.31 158.77,72.92 RT64.1
  TOP w0.635: RT73.1 156.74,72.31 156.72,72.28 ; 156.72,72.28 v1(156.72,70.06) ; 156.72,72.28 156.68,72.24
  LAYER3 w0.635: v1(156.72,70.06) 156.72,69.17 161.29,64.59 174.26,64.59 229.88,8.97 239.65,8.97 240.54,8.08 J5.2
IC-M: length 121.1
  TOP w0.508: 165.34,72.31 166.76,72.31 167.37,72.92 RT66.1
  TOP w0.635: 165.34,72.31 165.28,72.24 ; 165.34,72.31 v1(165.34,70.06) ; 165.34,72.31 RT74.1
  LAYER3 w0.635: v1(165.34,70.06) 169.15,66.25 174.64,66.25 230.64,10.24 251.08,10.24 253.24,8.08 253.24,6.3
IEXT-M: length 102.5
  TOP w0.508: 87.97,81.88 87.97,80.46 88.58,79.85 RT38.1
  TOP w0.635: 87.97,81.88 RT36.1 ; 87.97,81.88 v1(86.36,81.88) ; 87.97,81.88 87.91,81.95
  BOTTOM w0.635: J10.6 14.73,34.11 16.95,34.11 64.72,81.88 v1(86.36,81.88)
LED-G: length 28.8
  TOP w0.508: UT13.49 97.66,96.6 96.87,97.39 75.34,97.39 74.63,96.68 RT13.1
LED-R: length 44.3
  TOP w0.508: RT11.1 66.55,97.87 67.94,99.27 100.2,99.27 102.74,96.73 UT13.47
LED-Y: length 36.7
  TOP w0.508: UT13.48 100.2,96.73 98.55,98.38 71.5,98.38 70.59,97.46 RT12.1
QEA_A: length 83.5
  TOP w0.635: J10.14 23.47,35 44.05,55.58 83.56,55.58 UT13.89
QEA_B: length 84.9
  TOP w0.178: 84.83,56.85 UT13.90
  TOP w0.635: 84.83,56.85 43.52,56.85 22.95,36.27 8.63,36.27
QEA_I: length 83.4
  TOP w0.635: J10.18 22.42,37.54 43,58.12 83.82,58.12 UT13.91
QEB_A: length 87.6
  TOP w0.635: J10.22 19.38,40.08 49.99,70.69 83.69,70.69 UT13.94
QEB_B: length 89
  TOP w0.635: 8.63,41.35 18.86,41.35 49.46,71.96 UT13.95
QEB_I: length 87.6
  TOP w0.635: UT13.96 83.69,73.23 48.94,73.23 18.33,42.62 J10.26
SHUTDOWN+15V: length 125.7
  TOP w0.508: RT127.1 267.32,29.03 RT124.1 266.13,29.48 265.43,30.18 256.54,30.18 256.16,30.56 242.57,30.56 221.99,51.13
  TOP w0.635: v1(163.7,57.74) 187.2,57.74 193.8,51.13 221.99,51.13
  LAYER3 w0.381: UT13.13 164.97,50.37 164.97,52.66 164.72,52.91
  LAYER3 w0.635: 164.72,52.91 163.7,53.93 v1(163.7,57.74)
SHUTDOWN-15V: length 93.3
  TOP w0.508: RT115.1 228.34,38.67 RT117.1
  TOP w0.635: RT115.1 217.03,49.99 193.29,49.99 186.43,56.85 160.78,56.85 156.72,52.78 156.72,47.96 157.61,47.07 160.4,47.07 161.16,47.83 UT13.12
VA-M: length 45.8
  BOTTOM w0.635: J7.2 245.74,46.95 225.48,67.21 RB21.1
VA-P: length 33.4
  TOP w0.635: J7.1 245.58,39.45 RT99.1
VB-M: length 44.4
  BOTTOM w0.635: RB13.1 228.47,78.87 245.39,61.95 J7.4
VB-P: length 32
  TOP w0.635: J7.3 245.76,54.45 226.93,73.28 RT81.1
VC-M: length 43.1
  BOTTOM w0.635: J7.6 245.33,76.95 231.75,90.53 RB7.1
VC-P: length 30.7
  TOP w0.635: J7.5 245.46,69.45 229.97,84.94 RT35.1
VDC-M: length 24.1
  BOTTOM w0.635: RB1.1 242.82,102.19 J8.2
VDC-P: length 26
  TOP w0.635: J8.1 243.97,88.72 236.09,96.6 RT10.1
VSENSE-A: length 4.3
  TOP w0.508: UT13.27 RT18.2
  BOTTOM w0.635: RT18.2 UT13.27
VSENSE-B: length 4.3
  TOP w0.508: RT19.2 UT13.26
  BOTTOM w0.635: RT19.2 UT13.26
VSENSE-C: length 4.3
  TOP w0.508: RT20.2 UT13.25
  BOTTOM w0.635: RT20.2 UT13.25
VSENSE-DC: length 4.3
  TOP w0.508: RT21.2 UT13.24
  BOTTOM w0.635: RT21.2 UT13.24
N07282: length 2
  TOP w0.381: UT19.4 110.81,60.48 110.74,60.4 RT100.2
N07299: length 2
  TOP w0.381: UT19.12 118.97,59.82 118.98,59.82 RT101.1
N07508: length 2.1
  TOP w0.381: UT20.4 130.99,54.5 RT106.2
N07516: length 2
  TOP w0.381: RT89.1 131.64,64.12 UT20.12
N07693: length 2.3
  TOP w0.381: RT112.2 130.7,41.35 UT24.4
N07878: length 3.1
  TOP w0.254: UT25.4 182.17,36.51 182.24,36.44 182.24,35.59 182.41,35.43 RT120.2
N09835: length 5.2
  TOP w0.381: UT24.1 130.81,43.3 v1(130.81,44.27)
  BOTTOM w0.381: v1(130.81,44.27) 131.82,43.26 CB21.1 RB28.2
N10049: length 4.1
  TOP w0.381: UT24.7 v1(132.08,39.35)
  BOTTOM w0.381: v1(132.08,39.35) 132.82,40.08 RB29.2 CB23.1
N10085: length 8
  TOP w0.381: UT24.9 136.78,38.37 v1(136.78,37.54)
  BOTTOM w0.381: v1(136.78,37.54) 141.1,37.54 141.38,37.26 141.92,37.26 RB30.2 CB22.1
N10121: length 6.9
  TOP w0.381: v1(140.46,43.44) 140.02,43 137.79,43 137.39,42.6 UT24.15
  BOTTOM w0.381: CB20.1 RB27.2 140.53,43.51 v1(140.46,43.44)
N11382: length 3.9
  TOP w0.381: RT114.2 140.1,40.65 UT24.12
N11987: length 2.1
  TOP w0.381: RT111.2 182.92,44.55 182.88,44.51 182.88,43.37 UT25.12
N12714: length 4.2
  TOP w0.381: RT118.2 CT67.1 180.17,37.67 UT25.1
N12754: length 9.6
  TOP w0.381: 177.46,39.6 CT64.1 ; 177.46,39.6 RT113.2 ; 177.46,39.6 183.36,39.6 184.12,38.84 UT25.7
N16187: length 13.2
  TOP w0.508: CT23.2 105.25,80.18 UT3.4 104.14,82.88 UT3.1 103.34,82.92 98.21,88.06 RT24.1
N16636: length 2.8
  TOP w0.508: CT23.1 RT42.1 RT41.2
N16643: length 3.3
  TOP w0.508: RT42.2 103.83,80.49 UT3.3 103.11,80.75 CT15.2
N18013: length 2.8
  TOP w0.508: RT43.2 RT44.1 CT24.1
N18021: length 15.3
  TOP w0.508: CT24.2 111.83,80.18 UT4.4 110.73,82.88 UT4.1 109.93,83.06 106.55,86.44 103.5,86.44 102.74,87.2 RT25.1
N18093: length 3.3
  TOP w0.508: RT44.2 110.41,80.49 UT4.3 109.7,80.75 CT16.2
N18488: length 2.8
  TOP w0.508: RT45.2 RT46.1 CT25.1
N18496: length 18.8
  TOP w0.508: RT26.1 106.84,88.06 108.84,86.06 113.38,86.06 116.51,82.92 UT5.1 117.31,82.88 UT5.4 118.42,80.18 CT25.2
N18568: length 3.3
  TOP w0.508: RT46.2 117,80.49 UT5.3 116.28,80.75 CT17.2
N28683: length 20.8
  TOP w0.508: RT59.2 CT27.2 151.66,81.45 151.12,82 UT7.1 149.35,82.87 149.35,86.18 151.69,88.52 RT15.1
N28695: length 3.1
  TOP w0.508: RT59.1 CT27.1 153.26,79.76 UT7.4
N28775: length 3.2
  TOP w0.508: CT20.1 148.76,80.1 UT7.3 150.22,78.59 RT52.2
N28956: length 5.7
  TOP w0.508: RT63.2 151.61,75.71 150.27,75.71 RT62.2 RT52.1 RT51.2 147.47,76.94 CT31.1
N31299: length 5.7
  TOP w0.508: RT65.2 160.21,75.71 158.86,75.71 RT64.2 RT54.1 RT53.2 156.07,76.94 CT32.1
N31469: length 3.2
  TOP w0.508: CT21.1 157.36,80.1 UT8.3 158.82,78.59 RT54.2
N31505: length 14.2
  TOP w0.508: RT16.1 157.99,85.35 157.99,82.88 158.82,82.05 UT8.1 159.72,82 160.26,81.45 CT28.2 RT60.2
N31529: length 3.1
  TOP w0.508: UT8.4 161.86,79.76 CT28.1 RT60.1
N32358: length 5.7
  TOP w0.508: CT33.1 164.67,76.94 RT55.2 RT56.1 RT66.2 167.46,75.71 168.81,75.71 RT67.2
N32528: length 3.2
  TOP w0.508: CT22.1 165.95,80.1 UT9.3 167.42,78.59 RT56.2
N32564: length 14.1
  TOP w0.508: RT61.2 CT29.2 168.86,81.45 168.32,82 UT9.1 163.7,85.71 RT17.1
N32588: length 3.1
  TOP w0.508: UT9.4 170.46,79.76 CT29.1 RT61.1
N35636: length 1.5
  BOTTOM w0.635: RB24.1 RB23.2
N35646: length 1.5
  BOTTOM w0.635: RB25.1 RB24.2
N35650: length 1.5
  BOTTOM w0.635: RB26.1 RB25.2
N35794: length 1.5
  TOP w0.635: RT96.1 RT97.2
N35798: length 1.5
  TOP w0.635: RT95.1 RT96.2
N35802: length 1.5
  TOP w0.635: RT94.1 RT95.2
N35806: length 8.7
  TOP w0.381: RT93.2 193.74,63.12 RT90.1
  TOP w0.508: CT54.2 RT93.2
  TOP w0.635: RT90.1 193.88,63.07 195.83,63.07 197.29,61.62 RT94.2
N45499: length 1.5
  TOP w0.635: RT78.1 RT79.2
N45503: length 1.5
  TOP w0.635: RT77.1 RT78.2
N45507: length 1.5
  TOP w0.635: RT76.1 RT77.2
N45511: length 8.7
  TOP w0.381: RT68.1 193.74,74.78 RT75.2
  TOP w0.508: CT38.2 RT75.2
  TOP w0.635: RT68.1 193.86,74.75 195.32,74.75 196.8,73.28 RT76.2
N45813: length 1.5
  BOTTOM w0.635: RB16.1 RB15.2
N45817: length 1.5
  BOTTOM w0.635: RB17.1 RB16.2
N45821: length 1.5
  BOTTOM w0.635: RB18.1 RB17.2
N45825: length 8.6
  TOP w0.508: RT40.1 RT58.1 CT36.1
  TOP w0.635: RT58.1 193.85,77.46 v1(198.28,77.46)
  BOTTOM w0.635: RB18.2 v1(198.28,77.46)
N47166: length 1.5
  TOP w0.635: RT32.1 RT33.2
N47170: length 1.5
  TOP w0.635: RT31.1 RT32.2
N47174: length 1.5
  TOP w0.635: RT30.1 RT31.2
N47178: length 8.7
  TOP w0.381: RT29.2 193.74,86.44 RT28.1
  TOP w0.508: CT6.2 RT29.2
  TOP w0.635: RT30.2 197.33,84.94 195.83,86.44 193.84,86.44 RT28.1
N47480: length 1.5
  BOTTOM w0.635: RB10.1 RB9.2
N47484: length 1.5
  BOTTOM w0.635: RB11.1 RB10.2
N47488: length 1.5
  BOTTOM w0.635: RB12.1 RB11.2
N47492: length 8.8
  TOP w0.508: RT14.1 RT22.1 CT5.1
  TOP w0.635: RT22.1 193.95,89.02 v1(198.28,89.02)
  BOTTOM w0.635: RB12.2 v1(198.28,89.02)
N51028: length 1.5
  TOP w0.635: RT98.1 RT99.2
N51064: length 1.5
  BOTTOM w0.635: RB22.1 RB21.2
N51070: length 1.5
  TOP w0.635: RT97.1 RT98.2
N51074: length 1.5
  BOTTOM w0.635: RB23.1 RB22.2
N51202: length 1.5
  TOP w0.635: RT80.1 RT81.2
N51206: length 1.5
  TOP w0.635: RT79.1 RT80.2
N51246: length 1.5
  BOTTOM w0.635: RB14.1 RB13.2
N51250: length 1.5
  BOTTOM w0.635: RB15.1 RB14.2
N51378: length 1.5
  TOP w0.635: RT34.1 RT35.2
N51382: length 1.5
  TOP w0.635: RT33.1 RT34.2
N51422: length 1.5
  BOTTOM w0.635: RB8.1 RB7.2
N51426: length 1.5
  BOTTOM w0.635: RB9.1 RB8.2
N62914: length 5.7
  TOP w0.508: CT14.1 92.61,82.56 RT37.2 RT39.1 RT38.2 91.38,79.76 91.38,78.42 RT49.2
N63160: length 3.2
  TOP w0.508: CT19.1 95.76,81.27 UT10.3 94.25,79.8 RT39.2
N63220: length 15.9
  TOP w0.508: RT23.1 95.12,86.31 98.3,83.14 98.3,80.34 97.76,79.8 UT10.1 97.66,78.91 97.12,78.37 CT34.2 RT57.2
N63260: length 3.1
  TOP w0.508: RT57.1 CT34.1 95.42,76.77 UT10.4
N66752: length 44.6
  TOP w0.508: RT18.1 166.24,87.2 167.26,86.18 170.31,86.18 183.51,72.98 183.51,65.1 185.42,63.2 188.03,63.2 UT18.1 188.53,64.18 189.4,65.05 191.01,65.05 191.64,64.41 CT51.2 RT88.2
N66907: length 8.9
  TOP w0.508: RT87.1 RT88.1 CT51.1
  TOP w0.635: RT88.1 194,65.65 v1(198.28,65.65)
  BOTTOM w0.635: RB26.2 v1(198.28,65.65)
N66989: length 2.1
  TOP w0.508: RT87.2 191.24,67.21 UT18.4
N67029: length 2
  TOP w0.508: UT18.3 190.71,63.7 191.29,63.12 RT90.2
N74358: length 2
  TOP w0.508: RT68.2 191.29,74.78 190.71,75.36 UT12.3
N74448: length 31.9
  TOP w0.508: RT19.1 168.78,87.71 169.42,87.07 171.32,87.07 183.04,75.36 UT12.1 188.53,75.84 189.4,76.71 191.01,76.71 191.64,76.07 CT36.2 RT58.2
N74460: length 2.1
  TOP w0.508: UT12.4 191.24,78.87 RT40.2
N75234: length 2
  TOP w0.508: RT28.2 191.29,86.44 190.71,87.02 UT2.3
N75324: length 24.2
  TOP w0.508: RT20.1 171.4,88.52 173.1,86.82 188.34,86.82 UT2.1 188.53,87.5 189.4,88.37 191.01,88.37 191.64,87.73 CT5.2 RT22.2
N75336: length 2.1
  TOP w0.508: UT2.4 191.24,90.53 RT14.2
N76078: length 8.8
  TOP w0.381: RT3.1 193.74,98.1 RT4.2
  TOP w0.508: CT3.2 RT4.2
  TOP w0.635: RT5.2 197.23,96.6 195.71,98.12 193.87,98.12 RT3.1
N76134: length 2
  TOP w0.508: UT1.3 190.71,98.68 191.29,98.1 RT3.2
N76224: length 27.5
  TOP w0.508: RT2.2 CT2.2 191.64,99.39 191.01,100.03 189.4,100.03 188.53,99.16 UT1.1 186.18,96.33 186.18,92.28 182.42,88.52 RT21.1
N76236: length 2.1
  TOP w0.508: UT1.4 191.24,102.19 RT1.2
N76260: length 9
  TOP w0.508: CT2.1 RT2.1 RT1.1
  TOP w0.635: v1(198.28,100.5) 194.13,100.5 RT2.1
  BOTTOM w0.635: RB6.2 v1(198.28,100.5)
N78650: length 2.8
  TOP w0.508: CT26.1 RT48.1 RT47.2
N78658: length 17.7
  TOP w0.508: CT26.2 125,80.18 UT6.4 123.89,82.88 UT6.1 123.09,82.92 117.96,88.06 RT27.1
N78724: length 3.3
  TOP w0.508: RT48.2 123.58,80.49 UT6.3 122.86,80.75 CT18.2
N79088: length 15.6
  TOP w0.381: RT83.1 RT82.2 ; RT82.2 126.78,73.32 124.59,75.52 121.54,75.52 121.16,75.9 121.16,79.07 121.54,79.45 122.13,79.45 RT47.1 ; RT82.2 CT43.2
N88263: length 1.4
  TOP w0.635: DT5.1 RT110.2
N88433: length 1.4
  TOP w0.635: DT4.1 RT109.2
N88603: length 1.9
  TOP w0.508: RT138.2 DT12.1
N88777: length 1.7
  TOP w0.508: DT11.1 RT137.2
N93191: length 1.4
  TOP w0.508: RT11.2 DT1.1
N93195: length 1.4
  TOP w0.508: RT13.2 DT3.1
N93199: length 1.4
  TOP w0.508: RT12.2 DT2.1
N95779: length 19.8
  TOP w0.254: UT29.13 235.56,28.4 236.31,27.65 239.31,27.65 RT123.1
  TOP w0.381: RT128.1 241.32,28.34 RT123.1
  TOP w0.508: RT128.1 241.36,30.37 235.08,36.65 UT28.3
